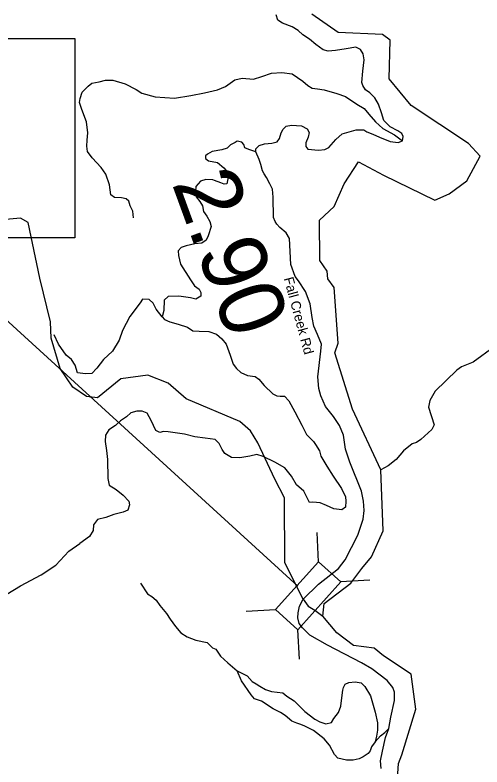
# Model space of a CAD drawing. Extents: x 1248224 to 1454986, y 825081 to 985870.
# Drawn here: x 1280820 to 1284414, y 902200 to 907992 of the extents above; entities that cross this region are included whole.
import ezdxf

# ---------------------------------------------------------------- set-up
doc = ezdxf.new("R2010")
doc.units = 0
for name, color, linetype in [('Exist Hydrographic Creek Single Shore', 7, 'Continuous'), ('Exist Hydrographic Misc Water Feature', 7, 'Continuous'), ('Exist Road Non-System Type 51', 7, 'Continuous'), ('Exist Road Secondary Mileage Hundredths English Label', 7, 'Continuous'), ('Exist Road Secondary Structure Standard Bridge CELL', 7, 'Continuous'), ('Exist Road Secondary Structure Standard Bridge Number Label', 7, 'Continuous'), ('Exist Road Secondary Type 51 Attributed', 7, 'Continuous'), ('Exist Road Secondary Type 51 Label', 7, 'Continuous')]:
    doc.layers.add(name, color=color, linetype=linetype)

msp = doc.modelspace()

# ---------------------------------------------------------------- linework, layer by layer
at = {"layer": 'Exist Hydrographic Creek Single Shore'}
for points in [[(1283490.1, 903729), (1283562.3, 903819.3), (1283652.6, 904018), (1283634.5, 904487.8), (1283417.9, 904957.5), (1283281, 905391), (1283307.1, 905465.9), (1283276, 905893.2), (1283228, 905959.9), (1283221.1, 906019.1), (1283165.1, 906102.3), (1283164.1, 906411), (1283275, 906517), (1283354, 906692.7), (1283462.2, 906862.6), (1283656.1, 906758.9), (1284052, 906567.1), (1284161, 906614.2), (1284298.3, 906715.9), (1284400.9, 906904.7), (1284310.7, 907002.2), (1283869, 907296.3), (1283699, 907500), (1283706.8, 907798.9), (1283648.8, 907842.7), (1283308, 907859.1), (1283103.1, 907997.8)], [(1283038.1, 903493.2), (1282897.6, 903772.6)], [(1283756.1, 901993.5), (1283770.2, 902226.3), (1283796.1, 902294.7), (1283905.4, 902645), (1283869.2, 902916), (1283657.1, 903055.8), (1283583.1, 903116.4), (1283425.1, 903135.9), (1283296.9, 903233.6), (1283189.1, 903360.6), (1283200.1, 903458.9), (1283403.2, 903615.5), (1283490.1, 903729)], [(1283038.1, 903493.2), (1283075.9, 903437.9), (1283128.3, 903408.8), (1283189.1, 903360.6)]]:
    msp.add_lwpolyline(points, dxfattribs=at)
at = {"layer": 'Exist Hydrographic Misc Water Feature'}
for points in [[(1282897.6, 903772.6), (1282893.7, 904273.1), (1282820.1, 904416.7), (1282688, 904697), (1282632.1, 904790), (1282550, 904860.6), (1282138.1, 905036.3), (1281999.1, 905157.2), (1281842.1, 905219.4), (1281633, 905190.8), (1281454, 905043.4), (1281371, 905054.9), (1281264, 905125.9), (1281168, 905269.1), (1281098.1, 905503.5), (1281093, 905628.4), (1281010, 905964.9), (1280920, 906393.5), (1280863, 906427.5), (1280719.9, 906414)], [(1284508.2, 905435.3), (1284345.2, 905319.5), (1284256.3, 905283.5), (1284219.6, 905256.4), (1284053.5, 905094.8), (1284011.6, 905023.3), (1284002.4, 904971.8), (1284045.2, 904834.8), (1284028.1, 904799), (1283942.3, 904722.7), (1283909.6, 904699.5), (1283877.4, 904688.8), (1283810.1, 904634.2), (1283752.4, 904569.7), (1283691.1, 904519.3), (1283634.5, 904487.8)]]:
    msp.add_lwpolyline(points, dxfattribs=at)
at = {"layer": 'Exist Road Non-System Type 51'}
for points in [[(1281731.6, 906430.1), (1281726.4, 906481.7), (1281705.8, 906523.1), (1281695.4, 906559.3), (1281674.8, 906577.4), (1281638.6, 906585.1), (1281584.4, 906587.7), (1281558.5, 906608.4), (1281548.2, 906683.3), (1281519.8, 906766), (1281483.7, 906817.7), (1281413.9, 906892.7), (1281377.8, 906941.8), (1281372.6, 906983.1), (1281375.2, 907029.6), (1281380.4, 907083.9), (1281370, 907169.2), (1281333.9, 907264.8), (1281315.8, 907319.1), (1281321, 907350.1), (1281336.4, 907399.2), (1281382.9, 907445.7), (1281411.3, 907466.4), (1281467.6, 907478.3), (1281516.6, 907491.2), (1281573.5, 907491.2), (1281666.4, 907462.8), (1281751.7, 907418.8), (1281795.6, 907390.4), (1281898.9, 907362), (1282046.1, 907351.6), (1282172.6, 907372.3), (1282278.5, 907393), (1282379.2, 907416.3), (1282438.6, 907442.1), (1282510.9, 907493.8), (1282567.7, 907506.7), (1282655.5, 907499), (1282720.1, 907519.6), (1282795, 907545.5), (1282872.5, 907550.6), (1282952.5, 907540.3), (1283035.2, 907483.5), (1283073.9, 907449.9), (1283106.6, 907429.2), (1283147.9, 907424), (1283199.5, 907416.3), (1283297.7, 907387.8), (1283362.2, 907364.6), (1283450, 907305.1), (1283506.8, 907271.5), (1283543, 907227.6), (1283594.7, 907170.7), (1283651.5, 907119), (1283739.3, 907069.9), (1283803, 907023)], [(1282673.6, 906938.6), (1282618.9, 906957.3), (1282587.9, 906970.2), (1282580.2, 906996), (1282564.7, 907014.1), (1282528.5, 907021.9), (1282513, 907011.5), (1282479.5, 906993.4), (1282453.6, 906967.6), (1282412.3, 906954.7), (1282337.4, 906941.8), (1282301.3, 906921.1), (1282285.8, 906908.2), (1282285.8, 906887.5), (1282309, 906869.4), (1282378.7, 906856.5), (1282427.8, 906815.1), (1282456.2, 906781.5), (1282458.8, 906729.8), (1282451, 906691.1), (1282430.4, 906688.5), (1282404.6, 906698.8), (1282355.5, 906716.9), (1282342.6, 906722.1), (1282288.3, 906724.7), (1282247, 906711.7), (1282210.9, 906670.4), (1282208.3, 906636.8), (1282213.4, 906592.9), (1282241.9, 906556.7), (1282262.5, 906523.1), (1282270.3, 906479.1), (1282296.1, 906443), (1282319.3, 906401.6), (1282329.7, 906362.8), (1282306.4, 906290.5), (1282290.9, 906256.9), (1282257.4, 906236.2), (1282203.1, 906231), (1282136, 906215.5), (1282099.8, 906202.6), (1282076.6, 906176.8), (1282079.2, 906140.6), (1282094.7, 906073.4), (1282169.6, 905953.8), (1282200.6, 905907.3), (1282236.8, 905881.4), (1282249.7, 905855.6), (1282249.7, 905827.2), (1282210.9, 905803.9), (1282169.6, 905814.2), (1282081.8, 905827.2), (1281999.2, 905824.6), (1281968.2, 905796.1), (1281965.6, 905716), (1281952.7, 905666.9)], [(1281952.7, 905666.9), (1281906.2, 905726.4), (1281882.9, 905772.9), (1281852, 905801.3), (1281800.3, 905803.9), (1281782.2, 905775.5), (1281704.7, 905669.5), (1281647.9, 905563.5), (1281622.1, 905488.6), (1281570.5, 905403.3), (1281500.7, 905338.7), (1281449.1, 905271.5), (1281410.3, 905230.2), (1281361.3, 905227.6), (1281301.9, 905235.3), (1281283.8, 905294.8), (1281255.4, 905338.7), (1281214.1, 905372.3), (1281154.7, 905457.6), (1281121.1, 905530)], [(1281952.7, 905666.9), (1281970.8, 905646.2), (1282012.1, 905628.2), (1282076.6, 905610.1), (1282146.4, 905586.8), (1282187.7, 905561), (1282236.8, 905558.4), (1282311.6, 905555.8), (1282371, 905535.1), (1282412.4, 905498.9), (1282445.9, 905457.6), (1282476.9, 905372.3), (1282497.6, 905302.5), (1282523.4, 905268.9), (1282557, 905237.9), (1282608.6, 905214.7), (1282668, 905206.9), (1282696.4, 905186.2), (1282737.8, 905139.7), (1282804.9, 905075.1), (1282835.2, 905057.9), (1282861, 905055.3), (1282894.6, 905055.3), (1282928.2, 905021.7), (1282974.7, 904936.4), (1283026.3, 904833), (1283062.5, 904760.7), (1283116.7, 904706.4), (1283132.2, 904683.1), (1283163.2, 904636.6), (1283173.5, 904595.3), (1283219.7, 904516.2), (1283268.8, 904441.3), (1283333.4, 904345.6), (1283364.3, 904281), (1283366.9, 904247.4), (1283364.3, 904200.9), (1283335.9, 904180.2), (1283274, 904188), (1283217.1, 904213.8), (1283168.1, 904234.5), (1283111.3, 904239.7), (1283085.4, 904237.1)], [(1283085.4, 904237.1), (1283041.5, 904325), (1282987.3, 904374.1), (1282948.6, 904441.3), (1282896.9, 904503.3), (1282819.4, 904547.2), (1282729, 904591.1), (1282680, 904606.7), (1282628.3, 904593.7), (1282550.8, 904580.8), (1282486.3, 904583.4), (1282434.6, 904614.4), (1282414, 904645.4), (1282390.7, 904691.9), (1282359.7, 904723), (1282282.3, 904733.3), (1282204.8, 904743.6), (1282124.7, 904764.3), (1281998.2, 904782.4), (1281963.3, 904784.4), (1281934.9, 904776.6), (1281903.9, 904792.1), (1281867.7, 904869.6), (1281836.7, 904926.5), (1281798, 904942), (1281756.7, 904942), (1281710.2, 904929.1), (1281676.6, 904898.1), (1281632.7, 904867.1), (1281594, 904830.9), (1281542.3, 904797.3), (1281516.5, 904755.9), (1281513.9, 904706.8), (1281524.2, 904637), (1281532, 904569.8), (1281534.6, 904422.5), (1281544.9, 904370.8), (1281599.1, 904337.2), (1281653.4, 904293.3), (1281694.5, 904247.6), (1281699.7, 904219.2), (1281686.8, 904177.8), (1281653.2, 904162.3), (1281580.9, 904144.2), (1281518.9, 904121), (1281454.4, 904105.5), (1281423.4, 904064.1), (1281420.8, 904022.8), (1281392.4, 903976.2), (1281318.9, 903922.5)], [(1280635.6, 903460), (1280861, 903596), (1281021.3, 903679), (1281132.9, 903753.5), (1281233.1, 903862.4), (1281318.9, 903922.5)], [(1281784.9, 903616.2), (1281839.1, 903533.5), (1281872.7, 903512.8), (1281906.3, 903484.4), (1281934.7, 903443.1), (1281986.3, 903383.6), (1282014.7, 903339.7), (1282056.1, 903282.8), (1282094.8, 903233.7), (1282143.9, 903202.7), (1282211, 903176.9), (1282298.8, 903158.8), (1282340.1, 903117.4), (1282366, 903107.1), (1282402.1, 903052.8), (1282458.9, 903001.1), (1282528.7, 902941.7), (1282606.1, 902902.9), (1282644.9, 902859), (1282675.9, 902840.9), (1282704.3, 902822.8), (1282748.2, 902797), (1282794.7, 902781.4), (1282879.9, 902771.1), (1282910.9, 902745.3), (1282967.7, 902709.1), (1283050.3, 902626.4), (1283126.7, 902568.5), (1283165.5, 902547.9), (1283212, 902532.4), (1283255.9, 902542.7), (1283273.9, 902573.7), (1283310.1, 902620.2), (1283328.2, 902669.3), (1283335.9, 902733.9), (1283343.7, 902790.8), (1283348.8, 902811.5), (1283361.8, 902837.3), (1283390.2, 902850.2), (1283436.6, 902855.4), (1283483.1, 902847.7), (1283511.5, 902819.2), (1283555.4, 902746.9), (1283591.6, 902622.8), (1283609.7, 902540.1), (1283609.7, 902483.3), (1283601.9, 902436.7), (1283591.6, 902392.8)], [(1283591.6, 902392.8), (1283563.2, 902354), (1283552.9, 902325.6), (1283537.4, 902304.9), (1283498.6, 902279.1), (1283467.6, 902263.6), (1283421.2, 902253.2), (1283372.1, 902253.2), (1283304.9, 902268.7), (1283279.1, 902297.2), (1283240.4, 902367), (1283199.1, 902416.1), (1283116.4, 902480.7), (1283049.3, 902514.3), (1283020.9, 902527.2), (1282989.9, 902537.5), (1282951.1, 902553), (1282899.5, 902597), (1282863.3, 902620.2), (1282806.5, 902648.7), (1282716.1, 902708.1), (1282661.9, 902726.2), (1282636.1, 902754.6), (1282563.7, 902863.2), (1282528.7, 902941.7)], [(1283591.6, 902392.8), (1283632.9, 902439.3), (1283666.5, 902465.2), (1283697.1, 902496.1)]]:
    msp.add_lwpolyline(points, dxfattribs=at)
at = {"layer": 'Exist Road Secondary Structure Standard Bridge CELL'}
for p, q in [((1283156.3, 903780), (1283144.3, 904006.1)), ((1283324.7, 903628.7), (1283550.7, 903640.7)), ((1282598, 903400.1), (1282824.1, 903412.1)), ((1283008.3, 903031.2), (1282996.3, 903257.3))]:
    msp.add_line(p, q, dxfattribs=at)
msp.add_lwpolyline([(1282824.1, 903412.1), (1283155.5, 903780.8), (1283327.7, 903625.9), (1282996.3, 903257.3)], close=True, dxfattribs=at)
at = {"layer": 'Exist Road Secondary Structure Standard Bridge Number Label'}
msp.add_line((1282996, 903592.4), (1280155.4, 906188.7), dxfattribs=at)
msp.add_lwpolyline([(1277564.4, 907812.1), (1281280.3, 907812.1), (1281280.3, 906275.7), (1277564.4, 906275.7)], close=True, dxfattribs=at)
at = {"layer": 'Exist Road Secondary Type 51 Attributed'}
for points in [[(1282932.6, 906270.2), (1282905.5, 906314.8), (1282858.9, 906355.6), (1282835.5, 906381.5), (1282821, 906400.8), (1282808.9, 906433.4), (1282806.4, 906588.1), (1282801.6, 906651), (1282779.9, 906692.1), (1282755.7, 906740.4), (1282736.4, 906769.4), (1282724.3, 906791.2), (1282712.2, 906841.9), (1282697.7, 906880.6), (1282673.6, 906938.6), (1282674, 906962.5), (1282698.1, 906986.7), (1282739.2, 907001.2), (1282797.2, 907006), (1282838.2, 907015.7), (1282855.1, 907042.3), (1282867.2, 907085.8), (1282884.1, 907112.4), (1282905.9, 907136.6), (1282946.9, 907143.8), (1283024.2, 907139), (1283067.7, 907114.8), (1283084.6, 907088.2), (1283075, 907052), (1283058.1, 907008.5), (1283058.1, 906979.4), (1283072.5, 906960.1), (1283154.7, 906950.4), (1283205.4, 906955.3), (1283235.3, 906972.2), (1283288.5, 907032.6), (1283336.8, 907076.1), (1283445.5, 907107.6), (1283503.5, 907107.6), (1283527.6, 907093.1), (1283573.5, 907073.7), (1283624.2, 907052), (1283706.4, 907018.1), (1283769.2, 907010.9), (1283803, 907023), (1283807.8, 907056.8), (1283798.2, 907078.6), (1283766.8, 907100.3), (1283707, 907130.8), (1283658.7, 907179.1), (1283639.4, 907239.5), (1283617.7, 907304.8), (1283588.7, 907355.6), (1283550, 907394.3), (1283518.6, 907416), (1283496.9, 907449.9), (1283489.6, 907471.6), (1283496.9, 907561.1), (1283506.5, 907648.1), (1283499.3, 907694), (1283480, 907727.9), (1283443.7, 907744.8), (1283368.8, 907732.7), (1283286.7, 907718.2), (1283231.2, 907713.4), (1283192.5, 907725.5), (1283134.5, 907764.2), (1283086.2, 907805.3), (1283036, 907840.7), (1282999.8, 907872.1), (1282953.9, 907901.2), (1282879, 907930.2), (1282842.8, 907951.9), (1282830.7, 907993)], [(1283038.1, 903493.2), (1283155.3, 903609.1), (1283310.4, 903729.4), (1283360.8, 903795.3), (1283459.6, 903986.4), (1283498.4, 904108.6), (1283506.2, 904176.5), (1283502.3, 904248.3), (1283486.8, 904324), (1283395.7, 904549), (1283364.7, 904649), (1283349.2, 904755.7), (1283318.2, 904831.4), (1283271.6, 904899.3), (1283209.6, 904976.9), (1283174.7, 905060.3), (1283159.2, 905116.6), (1283151.5, 905206.4), (1283174.8, 905402.3), (1283178.7, 905456.7), (1283147.7, 905532.3), (1283118.6, 905596.3), (1283107, 905662.3), (1283091.4, 905767.1), (1283054.6, 905862.1), (1283000.4, 905944.7), (1282977.2, 905977.7), (1282942.3, 906071.4), (1282932.6, 906270.2)], [(1283636.7, 902189.1), (1283631.9, 902247.1), (1283648.8, 902322.1), (1283670.5, 902428.4), (1283697.1, 902496.1), (1283711.6, 902582.6), (1283740.5, 902713.1), (1283740.5, 902776), (1283728.5, 902812.2), (1283685, 902865.4), (1283566.6, 902957.3), (1283485.3, 903002.1), (1283224.4, 903137.5), (1283089.1, 903214.9), (1283033.5, 903272.9), (1283007.1, 903306), (1282997.4, 903347.7), (1282998.4, 903388.4), (1283008.1, 903438.9), (1283038.1, 903493.2)]]:
    msp.add_lwpolyline(points, dxfattribs=at)

# ---------------------------------------------------------------- texts
at = {"layer": 'Exist Road Secondary Mileage Hundredths English Label'}
msp.add_text('2.90', height=500, rotation=290.06537, dxfattribs=at).set_placement((1282024.3, 906697.6))
at = {"layer": 'Exist Road Secondary Type 51 Label'}
msp.add_text('Fall Creek Rd', height=75, rotation=285.07716, dxfattribs=at).set_placement((1282888, 905963.1))

doc.saveas('drawing.dxf')
